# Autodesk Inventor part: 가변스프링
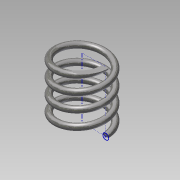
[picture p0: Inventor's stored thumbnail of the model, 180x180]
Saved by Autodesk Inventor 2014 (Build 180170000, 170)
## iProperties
Created: 2015-04
Part Number: 가변스프링
Material: 강철, 탄소
Document SubType Name: Modeling
Designer: Administrator
Density: 7.87 g/cm^3
Appearance: 반연마
Mass: 4.86811 g
Surface Area: 12.6122 cm^2
Volume: 0.618565 cm^3
Author: Administrator
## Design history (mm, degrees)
sketch "스케치1"
  geometry: L1 (0, 0)-(8, 0); L2 (8, 0)-(8, 20.5); L3 (8, 20.5)-(0, 20.5); L4 (0, 20.5)-(0, 0); C1 r 1 at (8, 0)
  constraints: 8 end point, 2 parallel, 1 centre point, 1 coincident, 1 horizontal, 1 perpendicular
  dimensions: "d0" = 16 diameter of L2 L4; "d1" = 20.49951 distance between parallel lines of L1 L3 (derived); "d2" = 2 diameter of C1
feature "코일1" pitch "d3" = 10; turns "d5" = 4; dims "d4" = 20.49951 (= d1), "d6" = 0, angle "d7" = 90 deg, angle "d8" = 90 deg, "d9" = 0, "d10" = 0
sketch "스케치2"
  geometry: L1 (-9, 0)-(-7, 0) reference; 1 further point
  constraints: 1 horizontal alignment
extrude "돌출1" cut sketch "스케치2" stored distance "d11" = 10; taper "d12" = 0 deg
node "작업 평면1"
sketch "스케치3"
  geometry: L1 (9, 0)-(7, 0) reference; 1 further point
  constraints: 1 horizontal alignment
extrude "돌출2" cut sketch "스케치3" stored distance "d13" = 10; taper "d14" = 0 deg
node "솔리드1"
node "절단 모서리 투영1"
node "절단 모서리 투영2"
